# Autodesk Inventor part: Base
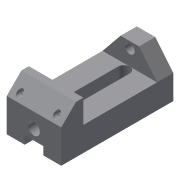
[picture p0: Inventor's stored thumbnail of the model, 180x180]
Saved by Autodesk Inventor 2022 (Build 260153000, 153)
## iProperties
Created: 2002-02
Part Number: Base
Document SubType Name: Modeling
Designer: ***
Density: 1 g/cm^3
Material: Generic
Appearance: Default
Control State: 0
Master: False
Checked Out: False
Shininess: 77.0
Length Units: 11269
Angle Units: 11279
Time Units: 11290
Mass Units: 11283
Length Display Precision: 3
Angle Display Precision: 2
Density: 0.0
Volumn: 0.0
Area: 0.0
PropertySet Name: Model Information
Author: ***
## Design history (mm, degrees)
sketch "Sketch2"
  geometry: L1 (-63.961, -4.254)-(-63.961, -37.254); L2 (-63.961, -37.254)-(88.039, -37.254); L3 (88.039, -37.254)-(88.039, 7.746); L4 (88.039, 7.746)-(68.039, 27.746); L5 (68.039, 27.746)-(58.039, 27.746); L6 (58.039, 27.746)-(58.039, -4.254); L7 (58.039, -4.254)-(-63.961, -4.254)
  constraints: 14 end point, 4 parallel, 1 perpendicular, 1 vertical
  dimensions: "d7" = 10 distance of L4.end L5.end; "d8" = 135 deg angle of L3 L4; "d9" = 33 distance of L1.start L1.end; "d10" = 152 distance of L1.end L2.end; "d11" = 65 distance between parallel lines of L5 L2; "d21" = 30 distance between parallel lines of L3 L6
extrude "Extrusion1" new body sketch "Sketch2" stored distance "d13" = 74; taper "d14" = 0 deg
sketch "Sketch3"
  geometry: L1 (0, 74)-(0, 0) reference; L2 (0, 0)-(-30, 24.5); L3 (-30, 24.5)-(-30, 49.5); L4 (-30, 49.5)-(0, 74); C1 r 6.5 at (-21, 37)
  constraints: 6 end point, 1 centre point, 1 equal length, 1 parallel
  dimensions: "d15" = 25 distance of L2.end L3.end; "d16" = 30 distance between parallel lines of L3 L1; "d17" = 13 diameter of C1; "d18" = 9 distance from line of L3 C1.centre
extrude "Extrusion2" join sketch "Sketch3" distance "d19" = 22; taper "d20" = 0 deg
sketch "Sketch4"
  geometry: L1 (0, 0)-(0, 74) reference; L2 (0, 0)-(45, 0) reference; C1 r 8 at (25, 37)
  constraints: 1 centre point
  dimensions: "d22" = 16 diameter of C1; "d23" = 25 distance from line of L1 C1.centre; "d24" = 37 distance from line of L2 C1.centre
extrude "Extrusion3" cut sketch "Sketch4" distance "d25" = 13; taper "d26" = 0 deg
sketch "Sketch5"
  geometry: L1 (45, 74)-(0, 74) reference; L2 (65, 0)-(65, 74) reference; 1 further point
  dimensions: "d27" = 12 distance from line of point (51, 62) L1; "d28" = 14 distance from line of L2 point (51, 62)
hole "Hole1" sketch "Sketch5" at (51, 62) diameter "d29" = 6; stored, may be unused: countersink angle "d33" = 82 deg, drill point angle "d35" = 0 deg; dims "d30" = 6, "d31" = 8, "d32" = 10, "d34" = 30
mirror "Mirror1"
sketch "Sketch6"
  geometry: L1 (100, 0)-(100, 74) reference; L2 (100, 74)-(0, 74) reference; L3 (14, 45)-(92, 45); L4 (92, 29)-(14, 29); A1 r 8 centre (92, 37) between (92, 29) and (92, 45); A2 r 8 centre (14, 37) between (14, 45) and (14, 29)
  constraints: 4 end point, 4 point on circle, 4 tangent, 2 centre point, 1 horizontal, 1 parallel
  dimensions: "d36" = 8 radius of A2; "d37" = 78 distance of L4.start L4.end; "d38" = 8 distance from line of L1 A1.centre; "d39" = 37 distance from line of L2 A2.centre
extrude "Extrusion4" cut sketch "Sketch6" extent not by distance; stored distance "d40" = 13; taper "d41" = 0 deg
sketch "Sketch7"
  geometry: L1 (0, 49.5)-(11, 49.5); L2 (11, 49.5)-(11, 24.5); L3 (11, 24.5)-(0, 24.5); L4 (0, 24.5)-(0, 49.5); L5 (45, 74)-(0, 74) reference; L6 (0, 0)-(0, 74) reference
  constraints: 8 end point, 2 parallel, 1 collinear, 1 horizontal, 1 perpendicular
  dimensions: "d42" = 25 distance of L3.end L1.start; "d43" = 11 distance of L1.start L1.end; "d44" = 24.5 distance between parallel lines of L5 L1
extrude "Extrusion5" cut sketch "Sketch7" extent not by distance; stored distance "d45" = 13; taper "d46" = 0 deg
body "Solid1"
